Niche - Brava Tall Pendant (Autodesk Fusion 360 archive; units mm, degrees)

design "Brava Tall" references "PCB Single Pendant Canopy"
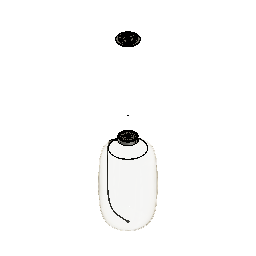
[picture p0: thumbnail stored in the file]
base_feature "Base Feature"
external_derived "ExternalDerived1" bodies "Set Screw", "Strain Relief", "Lead-1", "Lead-2", "Lead-2.1", "Lead-1.1", "Coax", "Stem"
move "Move1"
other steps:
derived_base_feature "Derived Base Feature" bodies "Set Screw", "Strain Relief", "Lead-1", "Lead-2", "Lead-2.1", "Lead-1.1", "Coax", "Stem"
create_component "CreateComponent1"
named bodies: "Set Screw", "Strain Relief", "Lead-1", "Lead-2", "Lead-2.1", "Lead-1.1", "Coax", "Stem", "Strain Relief Cap", "Nylon Gripper (2)", "Cap", "Thumbscrew (1)", "Thumbscrew (2)", "Thumbscrew (3)", "Niche-PCB", "FJ-Plug Cover", "FJ-Plug", "FJ-Plug1.1", "FJ-Plug1.2", "FJ-Plug1.3", "Fj-Plug1.4", "Canopy", "FJ-Port", "FJ-Port1.1", "Spacer", "Universal Mount", "FJ-Port Cover", "Diffuser"

design "FJ Plug - PCB-Hardware"
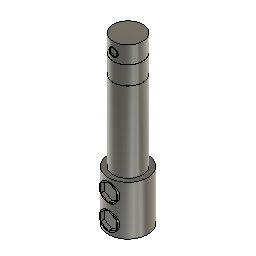
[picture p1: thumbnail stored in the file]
sketch "Sketch1" plane through (0, 0, 0) normal (0, 0, 1) x axis (1, 0, 0)
  circle C1 centre (0, 0) radius 3.048
  point P1 (0, 0)
  point P2 (0, 0)
  coincident P1 P2
  dimension "d1" diameter C1 = 6.096
extrude "Extrude1" new body sketch "Sketch1" along normal blind 34.036
sketch "Sketch2" plane through (0, 0, 0) normal (0, 0, 1) x axis (1, 0, 0)
  circle C1 centre (0, 0) radius 4.064
  point P1 (0, 0)
  point P2 (0, 0)
  coincident P1 P2
  dimension "d4" diameter C1 = 8.128
extrude "Extrude2" add sketch "Sketch2" along normal blind 10.16
sketch "Sketch3" plane through (0, 0, 0) normal (0, 1, 0) x axis (1, 0, 0)
  line L1 (6.35, 0) -> (-6.35, 0)
  line L2 (6.35, -30.48) -> (-6.35, -30.48)
  line L3 (2.54, -30.48) -> (6.35, -30.48)
  line L4 (2.54, -26.67) -> (2.54, -30.48)
  line L5 (6.35, -26.67) -> (2.54, -26.67)
  line L6 (6.35, -30.48) -> (6.35, -26.67)
  horizontal L1
  horizontal L3
  vertical L4
  horizontal L5
  vertical L6
  dimension "d7" = 30.48
revolve "Revolve1" sketch "Sketch3" AlongAngle 360
sketch "Sketch4" plane through (0, 0, 0) normal (0, 1, 0) x axis (1, 0, 0)
  line L1 (2.54, -30.48) -> (3.048, -30.48)
  line L2 (2.54, -26.67) -> (2.54, -30.48)
  line L3 (3.048, -26.67) -> (2.54, -26.67)
  line L4 (3.048, -30.48) -> (3.048, -26.67)
  horizontal L1
  vertical L2
  horizontal L3
  vertical L4
revolve "Revolve2" sketch "Sketch4" AlongAngle 360
chamfer "Chamfer1" distance 0.0254
chamfer "Chamfer2" distance 0.0254
hole "Hole1" HoleDepth 33.401 HoleDiameter 4.826 TipAngle 180
hole "Hole2" HoleDepth 3.81 HoleDiameter 1.778 TipAngle 180
hole "Hole3" HoleDepth 3.81 HoleDiameter 3.81 TipAngle 180
hole "Hole4" HoleDepth 3.81 HoleDiameter 3.81 TipAngle 180
sketch "Sketch5" plane through (0, 0, 0) normal (0, 1, 0) x axis (1, 0, 0)
  circle C1 centre (0, -32.0802) radius 0.889
  dimension "d24" diameter C1 = 1.778
extrude "Extrude3" new body sketch "Sketch5" along normal blind 1.778
move "Move1"
sketch "Sketch6" plane through (0, -3.048, 0) normal (0, -1, 0) x axis (1, 0, 0)
  line L1 (0.7259, 31.6611) -> (0, 31.242)
  line L2 (0.7259, 32.4993) -> (0.7259, 31.6611)
  line L3 (0, 32.9184) -> (0.7259, 32.4993)
  line L4 (-0.7259, 32.4993) -> (0, 32.9184)
  line L5 (-0.7259, 31.6611) -> (-0.7259, 32.4993)
  line L6 (0, 31.242) -> (-0.7259, 31.6611)
  circle C1 centre (0, 32.0802) radius 0.889
  point P2 (0, 32.0802)
  point P9 (0, 32.0802)
  coincident P2 P9
extrude "Extrude4" cut sketch "Sketch6" profile of L1 L2 L3 L4 L5 L6 against normal blind 0.254
sketch "Sketch7" plane through (0, 0, 0) normal (0, 1, 0) x axis (1, 0, 0)
  circle C1 centre (0, -2.4384) radius 1.905
  circle C2 centre (0, -7.5565) radius 1.905
  dimension "d29" diameter C1 = 3.81
  dimension "d30" diameter C2 = 3.81
extrude "Extrude5" new body sketch "Sketch7" profile of C2 along normal blind 3.81
move "Move2"
sketch "Sketch8" plane through (0, -4.064, 0) normal (0, -1, 0) x axis (1, 0, 0)
  line L1 (1.5948, 6.6357) -> (0, 5.715)
  line L2 (1.5948, 8.4772) -> (1.5948, 6.6357)
  line L3 (0, 9.398) -> (1.5948, 8.4772)
  line L4 (-1.5948, 8.4772) -> (0, 9.398)
  line L5 (-1.5948, 6.6357) -> (-1.5948, 8.4772)
  line L6 (0, 5.715) -> (-1.5948, 6.6357)
  circle C1 centre (0, 7.5565) radius 1.905
  point P2 (0, 7.5565)
  point P9 (0, 7.5565)
  coincident P2 P9
extrude "Extrude6" cut sketch "Sketch8" profile of L1 L2 L3 L4 L5 L6 against normal blind 0.762
copy_paste_bodies "CopyPasteBodies2"
move "Move4"
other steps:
base_feature "Base Feature"

design "Flask Petite"
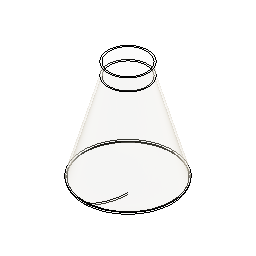
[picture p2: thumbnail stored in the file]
sketch "Sketch1" plane through (0, 0, 0) normal (1, 0, 0) x axis (0, 1, 0)
canvas "Canvas1"
sketch "Sketch2" plane through (0, 0, 0) normal (1, 0, 0) x axis (0, 1, 0)
  line L1 (-5.314, 187.093) -> (-57.384, 187.093)
  line L2 (-57.384, 155.343) -> (-57.384, 187.093)
  line L3 (-121.92, -71.12) -> (-57.384, 155.343)
  line L4 (-5.314, -112.5919) -> (-5.314, 187.093)
  curve K1 (-5.314, -112.5919) -> (-121.92, -74.8854)
  arc A1 centre (-115.3135, -73.0027) radius 6.8695 clockwise from (-121.92, -74.8854) to (-121.92, -71.12)
  point P2 (-57.384, 187.093)
  point P3 (-5.314, 187.093)
  point P4 (-57.384, 155.343)
  horizontal L1
  perpendicular L1 L2
  tangent L3 A1
  perpendicular L1 L4
  dimension "d1" distance P2 P3 = 52.07
  dimension "d2" distance P2 P4 = 31.75
revolve "Revolve1" sketch "Sketch2" AlongAngle 360
fillet "Fillet1" radius 5.08
shell "Shell1" innerThickness 4

design "PCB Single Pendant Canopy" references "PCB Cap", "Diffuser", "FJ Plug - PCB-Hardware", "Flask Petite", "PCB Canopy", "FJ Cover - PCB-Hardware"
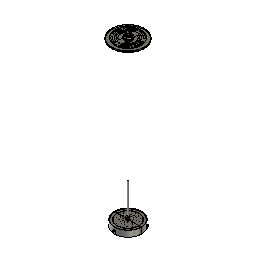
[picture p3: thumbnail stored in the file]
external_derived "ExternalDerived1" bodies "Nylon Gripper", "Set Screw", "Strain Relief", "Lead-1", "Lead-2", "Lead-2.1", "Lead-1.1", "Coax"
external_derived "ExternalDerived2" bodies "FJ-Plug Cover"
move "Move1"
move "Move2" TranslateX 3.175 TranslateY 0.254 TranslateZ 0
move "Move3" TranslateX 0 TranslateY 0 TranslateZ 1092.2
external_derived "ExternalDerived3" bodies "FJ-Plug", "FJ-Plug1.2", "FJ-Plug1.1", "FJ-Plug1.3", "Fj-Plug1.4"
move "Move4" TranslateX 0 TranslateY 0 TranslateZ 1117.6
external_derived "ExternalDerived4" bodies "Nylon Gripper", "Spacer", "Canopy", "FJ-Port", "FJ-Port1.1", "Universal Mount", "FJ-Port Cover", "Lead-1.1"
move "Move5"
move "Move6"
external_derived "ExternalDerived5" bodies "Diffuser"
move "Move7"
external_derived "ExternalDerived6" bodies "Thumbscrew (1)"
align "Align1"
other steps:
derived_base_feature "Derived Base Feature1"
derived_base_feature "Derived Base Feature2" bodies "FJ-Plug Cover"
derived_base_feature "Derived Base Feature3" bodies "FJ-Plug", "FJ-Plug1.1", "FJ-Plug1.2"
derived_base_feature "Derived Base Feature4" bodies "Body1 (1)", "Body1 (1) (1)", "Body2 (1)", "Body1 (2)", "Body1 (3)", "Body1 (4)", "Canopy", "FJ-Port"
derived_base_feature "Derived Base Feature5" bodies "Diffuser"
derived_base_feature "Derived Base Feature6" bodies "Body1", "Thumbscrew (1)"
named bodies: "Nylon Gripper", "Set Screw", "Strain Relief", "Lead-1", "Lead-2", "Lead-2.1", "Lead-1.1", "Coax", "Stem", "stem (2)", "Strain Relief Cap", "Nylon Gripper (2)", "Cap", "Thumbscrew (1)", "Thumbscrew (2)", "Thumbscrew (3)", "Niche-PCB", "FJ-Plug Cover", "FJ-Plug", "FJ-Plug1.1", "FJ-Plug1.2", "FJ-Plug1.3", "Fj-Plug1.4", "Body1 (1)", "Body1 (1) (1)", "Body2 (1)", "Body1 (2)", "Body1 (3)", "Body1 (4)", "Canopy", "FJ-Port", "FJ-Port1.1", "Spacer", "Universal Mount", "FJ-Port Cover", "Diffuser", "Body1"

design "FJ Female"
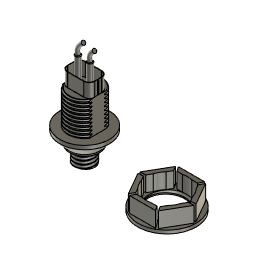
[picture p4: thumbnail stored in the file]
sketch "Sketch1" plane through (0, 0, 0) normal (0, 0, 1) x axis (1, 0, 0)
  circle C1 centre (0, 0) radius 4.445
  point P1 (0, 0)
  point P2 (0, 0)
  coincident P1 P2
  dimension "d1" diameter C1 = 8.89
extrude "Extrude1" new body sketch "Sketch1" along normal blind 6.858
sketch "Sketch2" plane through (0, 0, 6.858) normal (0, 0, 1) x axis (-1, 0, 0)
  circle C1 centre (0, 0) radius 4.445
  circle C2 centre (0, 0) radius 6.985
  point P1 (0, 0)
  point P3 (0, 0)
  coincident P1 P3
  dimension "d4" diameter C2 = 13.97
extrude "Extrude2" add sketch "Sketch2" along normal blind 1.27
work_plane "WorkPlane1" AlongDistance 5.08
sketch "Sketch3" plane through (0, 0, 13.208) normal (0, 0, 1) x axis (1, 0, 0)
  circle C1 centre (0, 0) radius 11.43
  point P1 (0, 0)
  point P2 (0, 0)
  coincident P1 P2
  dimension "d8" diameter C1 = 22.86
loft "Loft1" sketch "Sketch3"
extrude "Extrude3" add of existing geometry blind 1.778
sketch "Sketch4" plane through (0, 0, 14.986) normal (0, 0, 1) x axis (-1, 0, 0)
  circle C1 centre (0, 0) radius 11.43
  circle C2 centre (0, 0) radius 7.62
  point P1 (0, 0)
  point P3 (0, 0)
  coincident P1 P3
  dimension "d11" diameter C2 = 15.24
extrude "Extrude4" add sketch "Sketch4" profile of C2 along normal blind 15.24
sketch "Sketch5" plane through (0, 0, 30.226) normal (0, 0, 1) x axis (-1, 0, 0)
  line L1 (6.35, 0) -> (0, 0)
  line L2 (-6.35, 0) -> (0, 0)
  line L3 (6.35, -4.2121) -> (6.35, 0)
  line L4 (6.35, 4.2121) -> (6.35, 0)
  line L5 (-6.35, -4.2121) -> (-6.35, 0)
  line L6 (-6.35, 4.2121) -> (-6.35, 0)
  circle C1 centre (0, 0) radius 7.62
  point P2 (0, 0)
  point P3 (0, 0)
  point P5 (0, 0)
  point P7 (6.35, -4.2121)
  point P8 (6.35, 4.2121)
  point P9 (-6.35, -4.2121)
  point P10 (-6.35, 0)
  point P11 (-6.35, 4.2121)
  point P4 (6.35, 0)
  point P6 (-6.35, 0)
  coincident P2 P3
  horizontal L1
  coincident P2 P5
  parallel L1 L2
  coincident C1 P7
  perpendicular L1 L3
  coincident C1 P8
  perpendicular L1 L4
  coincident C1 P9
  perpendicular L2 L5
  coincident L2 P10
  perpendicular L2 L6
  coincident C1 P11
  dimension "d14" distance P3 P4 = 6.35
  dimension "d15" distance P5 P6 = 6.35
extrude "Extrude5" cut sketch "Sketch5" profile of C1 L3 L4 L5 L6 against normal blind 15.24
sketch "Sketch6" plane through (0, 0, 30.226) normal (0, 0, 1) x axis (-1, 0, 0)
  line L1 (-6.35, -4.2121) -> (-6.35, 4.2121)
  line L2 (6.35, 4.2121) -> (6.35, -4.2121)
  line L3 (-6.35, -4.2121) -> (6.35, -4.2121)
  line L4 (6.35, 4.2121) -> (-6.35, 4.2121)
  line L5 (6.35, -4.2121) -> (6.35, 4.2121)
  line L6 (-6.35, 4.2121) -> (-6.35, -4.2121)
  line L7 (-6.223, 4.064) -> (6.223, 4.064)
  line L8 (-6.223, -4.064) -> (-6.223, 4.064)
  line L9 (6.223, -4.064) -> (-6.223, -4.064)
  line L10 (6.223, 4.064) -> (6.223, -4.064)
  line L11 (-6.223, -4.064) -> (6.223, 4.064)
  line L12 (6.223, -4.064) -> (-6.223, 4.064)
  arc A1 centre (0, 0) radius 7.62 clockwise from (6.35, -4.2121) to (-6.35, -4.2121)
  arc A2 centre (0, 0) radius 7.62 clockwise from (-6.35, 4.2121) to (6.35, 4.2121)
  point P4 (6.35, -4.2121)
  point P7 (6.35, -4.2121)
  point P3 (-6.35, -4.2121)
  point P8 (-6.35, -4.2121)
  point P2 (-6.35, 4.2121)
  point P9 (-6.35, 4.2121)
  point P6 (6.35, 4.2121)
  point P10 (6.35, 4.2121)
  point P15 (0, 0)
  point P5 (0, 0)
  point P13 (-6.223, -4.064)
  point P14 (6.223, -4.064)
  point P12 (-6.223, 4.064)
  coincident P4 P7
  coincident P3 P8
  coincident P2 P9
  coincident P6 P10
  perpendicular L7 L8
  parallel L7 L9
  parallel L8 L10
  horizontal L7
  coincident L11 P15
  coincident L12 P15
  coincident P5 P15
  dimension "d18" distance P13 P14 = 12.446
  dimension "d19" distance P12 P13 = 8.128
extrude "Extrude6" add sketch "Sketch6" profile of L1 L2 L3 L4 L5 L6 L7 L8 L9 L10 along normal blind 6.35
fillet "Fillet1" radius 2.54
sketch "Sketch7" plane through (6.35, 0, 0) normal (1, 0, 0) x axis (0, 1, 0)
  line L1 (1.6721, 36.576) -> (1.6721, 30.226)
  line L2 (-1.6721, 36.576) -> (1.6721, 36.576)
  line L3 (-1.6721, 30.226) -> (-1.6721, 36.576)
  line L4 (-4.2121, 30.226) -> (-1.6721, 30.226)
  line L5 (-4.2121, 14.986) -> (-4.2121, 30.226)
  line L6 (4.2121, 14.986) -> (-4.2121, 14.986)
  line L7 (4.2121, 30.226) -> (4.2121, 14.986)
  line L8 (1.6721, 30.226) -> (4.2121, 30.226)
  line L9 (0.254, 36.576) -> (-0.2492, 36.576)
  line L10 (0.254, 30.226) -> (0.254, 36.576)
  line L11 (-0.2492, 30.226) -> (0.254, 30.226)
  line L12 (-0.2492, 36.576) -> (-0.2492, 30.226)
  point P10 (-0.2492, 36.576)
  horizontal L9
  vertical L10
  horizontal L11
  vertical L12
  coincident L2 P10
extrude "Extrude7" cut sketch "Sketch7" profile of L2 L9 L10 L11 L12 against normal blind 0.508
thread "Thread1"
fillet "Fillet2" radius 0.635
thread "Thread2"
sketch "Sketch8" plane through (0, 0, 30.226) normal (0, 0, 1) x axis (-1, 0, 0)
  line L1 (-6.223, -1.524) -> (-6.223, -0.254)
  line L2 (3.683, -4.064) -> (-3.683, -4.064)
  line L3 (6.223, 1.524) -> (6.223, -1.524)
  line L4 (-3.683, 4.064) -> (3.683, 4.064)
  line L5 (-6.223, 0.2492) -> (-6.223, 1.524)
  line L6 (-6.35, 0.2492) -> (-6.223, 0.2492)
  line L7 (-6.35, -0.254) -> (-6.35, 0.2492)
  line L8 (-6.223, -0.254) -> (-6.35, -0.254)
  arc A1 centre (-3.683, -1.524) radius 2.54 clockwise from (-3.683, -4.064) to (-6.223, -1.524)
  arc A2 centre (3.683, -1.524) radius 2.54 clockwise from (6.223, -1.524) to (3.683, -4.064)
  arc A3 centre (3.683, 1.524) radius 2.54 clockwise from (3.683, 4.064) to (6.223, 1.524)
  arc A4 centre (-3.683, 1.524) radius 2.54 clockwise from (-6.223, 1.524) to (-3.683, 4.064)
  circle C1 centre (3.048, 0) radius 1.27
  circle C2 centre (-2.54, 0) radius 1.27
  dimension "d26" diameter C1 = 2.54
  dimension "d27" diameter C2 = 2.54
extrude "Extrude8" add sketch "Sketch8" profile of C1 C2 along normal blind 11.43
sketch "Sketch9" plane through (0, 0, 0) normal (0, 1, 0) x axis (1, 0, 0)
  curve K1 (4.572, -46.99) -> (2.54, -41.656)
  curve K2 (-0.508, -47.752) -> (-3.048, -41.656)
pipe "Pipe1" SectionSize 1.778 SectionThickness 0.0762
pipe "Pipe2" SectionSize 1.778 SectionThickness 0.0762
sketch "Sketch10" plane through (0, 0, 0) normal (0, 0, 1) x axis (1, 0, 0)
  circle C1 centre (38.1, 0) radius 13.462
  dimension "d38" diameter C1 = 26.924
extrude "Extrude9" new body sketch "Sketch10" along normal blind 1.524
sketch "Sketch11" plane through (0, 0, 1.524) normal (0, 0, 1) x axis (-1, 0, 0)
  circle C1 centre (-38.1, 0) radius 13.462
  circle C2 centre (-38.1, 0) radius 9.271
  concentric C1 C2
  dimension "d41" diameter C2 = 18.542
extrude "Extrude10" cut sketch "Sketch11" profile of C2 against normal blind 7.62
sketch "Sketch12" plane through (0, 0, 1.524) normal (0, 0, 1) x axis (-1, 0, 0)
  line L1 (-24.9018, 0) -> (-31.5009, -11.43)
  line L2 (-31.5009, 11.43) -> (-24.9018, 0)
  line L3 (-44.6991, 11.43) -> (-31.5009, 11.43)
  line L4 (-51.2982, 0) -> (-44.6991, 11.43)
  line L5 (-44.6991, -11.43) -> (-51.2982, 0)
  line L6 (-31.5009, -11.43) -> (-44.6991, -11.43)
  line L7 (-27.3948, 0) -> (-32.7474, -9.271)
  line L8 (-32.7474, 9.271) -> (-27.3948, 0)
  line L9 (-43.4526, 9.271) -> (-32.7474, 9.271)
  line L10 (-48.8052, 0) -> (-43.4526, 9.271)
  line L11 (-43.4526, -9.271) -> (-48.8052, 0)
  line L12 (-32.7474, -9.271) -> (-43.4526, -9.271)
  circle C1 centre (-38.1, 0) radius 9.271
  circle C2 centre (-38.1, 0) radius 13.462
  point P2 (-38.1, 0)
  point P9 (-38.1, 0)
  point P16 (-38.1, 0)
  coincident P2 P9
  coincident P9 P16
extrude "Extrude11" add sketch "Sketch12" profile of L1 L2 L3 L4 L5 L6 L7 L8 L9 L10 L11 L12 along normal blind 7.112
thread "Thread3"
sketch "Sketch13" plane through (0, 0, 8.636) normal (0, 0, 1) x axis (-1, 0, 0)
  line L1 (-43.4526, -9.271) -> (-32.7474, -9.271)
  line L2 (-48.8052, 0) -> (-43.4526, -9.271)
  line L3 (-43.4526, 9.271) -> (-48.8052, 0)
  line L4 (-32.7474, 9.271) -> (-43.4526, 9.271)
  line L5 (-27.3948, 0) -> (-32.7474, 9.271)
  line L6 (-32.7474, -9.271) -> (-27.3948, 0)
  line L7 (-31.5009, -11.43) -> (-44.6991, -11.43)
  line L8 (-24.9018, 0) -> (-31.5009, -11.43)
  line L9 (-31.5009, 11.43) -> (-24.9018, 0)
  line L10 (-44.6991, 11.43) -> (-31.5009, 11.43)
  line L11 (-51.2982, 0) -> (-44.6991, 11.43)
  line L12 (-44.6991, -11.43) -> (-51.2982, 0)
sketch "Sketch14" plane through (0, 0, 8.636) normal (0, 0, 1) x axis (-1, 0, 0)
  circle C1 centre (-38.1, 0) radius 9.525
  dimension "d46" diameter C1 = 19.05
extrude "Extrude12" cut sketch "Sketch14" against normal blind 7.112
sketch "Sketch15" plane through (0, 0, 8.636) normal (0, 0, 1) x axis (-1, 0, 0)
  line L1 (-51.2982, 0) -> (-44.6991, 11.43)
  line L2 (-43.4526, 9.271) -> (-48.8052, 0)
  line L3 (-32.7474, 9.271) -> (-43.4526, 9.271)
  line L4 (-44.6991, 11.43) -> (-31.5009, 11.43)
  line L5 (-44.1911, 11.43) -> (-42.7995, 9.271)
  line L6 (-40.2139, 9.271) -> (-42.7995, 9.271)
  line L7 (-43.7181, 8.8112) -> (-45.0232, 10.8687)
  line L8 (-43.4526, 9.271) -> (-42.7995, 9.271)
  line L9 (-43.7181, 8.8112) -> (-43.4526, 9.271)
  line L10 (-45.0232, 10.8687) -> (-44.6991, 11.43)
  line L11 (-44.1911, 11.43) -> (-44.6991, 11.43)
  line L12 (-48.5398, -0.4598) -> (-50.9742, -0.5613)
  line L13 (-48.5398, -0.4598) -> (-48.8052, 0)
  line L14 (-48.8052, 0) -> (-48.4787, 0.5657)
  line L15 (-51.0442, 0.4399) -> (-48.4787, 0.5657)
  line L16 (-51.0442, 0.4399) -> (-51.2982, 0)
  line L17 (-50.9742, -0.5613) -> (-51.2982, 0)
  line L18 (-42.9217, -9.271) -> (-44.051, -11.43)
  line L19 (-42.9217, -9.271) -> (-43.4526, -9.271)
  line L20 (-43.4526, -9.271) -> (-43.7792, -8.7053)
  line L21 (-44.9531, -10.9901) -> (-43.7792, -8.7053)
  line L22 (-44.9531, -10.9901) -> (-44.6991, -11.43)
  line L23 (-44.051, -11.43) -> (-44.6991, -11.43)
  line L24 (-32.4819, -8.8112) -> (-31.1768, -10.8687)
  line L25 (-32.4819, -8.8112) -> (-32.7474, -9.271)
  line L26 (-32.7474, -9.271) -> (-33.4005, -9.271)
  line L27 (-32.0089, -11.43) -> (-33.4005, -9.271)
  line L28 (-32.0089, -11.43) -> (-31.5009, -11.43)
  line L29 (-31.1768, -10.8687) -> (-31.5009, -11.43)
  line L30 (-27.6603, 0.4598) -> (-25.2258, 0.5613)
  line L31 (-27.6603, 0.4598) -> (-27.3948, 0)
  line L32 (-27.3948, 0) -> (-27.7214, -0.5657)
  line L33 (-25.1558, -0.4399) -> (-27.7214, -0.5657)
  line L34 (-25.1558, -0.4399) -> (-24.9018, 0)
  line L35 (-25.2258, 0.5613) -> (-24.9018, 0)
  line L36 (-33.2783, 9.271) -> (-32.149, 11.43)
  line L37 (-33.2783, 9.271) -> (-32.7474, 9.271)
  line L38 (-32.7474, 9.271) -> (-32.4208, 8.7053)
  line L39 (-31.2469, 10.9901) -> (-32.4208, 8.7053)
  line L40 (-31.2469, 10.9901) -> (-31.5009, 11.43)
  line L41 (-32.149, 11.43) -> (-31.5009, 11.43)
  point P10 (-42.7995, 9.271)
  point P12 (-45.0232, 10.8687)
  point P13 (-43.7181, 8.8112)
  point P5 (-43.4526, 9.271)
  point P14 (-43.4526, 9.271)
  point P16 (-44.1911, 11.43)
  point P9 (-44.6991, 11.43)
  point P15 (-44.6991, 11.43)
  horizontal L6
  coincident L3 P10
  coincident L1 P12
  coincident L2 P13
  coincident P5 P14
  coincident L4 P16
  coincident P9 P15
  coincident L4 P16
  dimension "d50" distance P15 P16 = 0.508
  dimension "d54" C-Pattern1-Angle = 360
extrude "Extrude13" cut sketch "Sketch15" profile of L1 L2 L3 L4 L5 L7 L8 L9 L10 L11 L12 L13 L14 L15 L16 L17 L18 L19 L20 L21 L22 L23 L24 L25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 against normal blind 7.112

design "FJ Cover - PCB-Hardware"
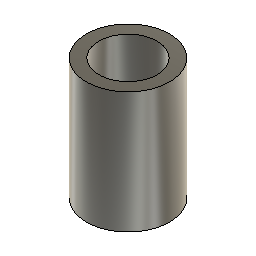
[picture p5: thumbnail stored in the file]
sketch "Sketch1" plane through (0, 0, 0) normal (0, 0, 1) x axis (1, 0, 0)
  circle C1 centre (0, 0) radius 6.35
  point P1 (0, 0)
  point P2 (0, 0)
  coincident P1 P2
  dimension "d1" diameter C1 = 12.7
extrude "Extrude1" new body sketch "Sketch1" along normal blind 18.542
hole "Hole1" HoleDepth 13.97 HoleDiameter 8.89 TipAngle 180
hole "Hole2" HoleDepth 13.97 HoleDiameter 3.556 TipAngle 180

design "PCB Canopy" references "Port Cover - PCB-Hardware", "Spacer - PCB-Hardware", "FJ Female", "FJ Cover - PCB-Hardware", "Canopy - PCB-Hardware", "Universal Mounting Bracket - PCB-Hardware"
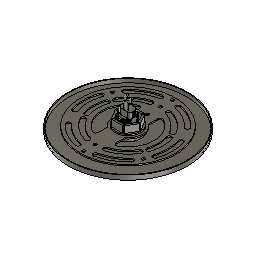
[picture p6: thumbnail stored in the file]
external_derived "ExternalDerived"
external_derived "ExternalDerived"
external_derived "ExternalDerived3" bodies "Body1 (1)"
external_derived "ExternalDerived4"
external_derived "ExternalDerived5"
move "Move1"
move "Move2"
move "Move3"
move "Move4"
move "Move5"
move "Move6"
move "Move7"
move "Move8"
external_derived "ExternalDerived6"
align "Align1"
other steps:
derived_base_feature "Derived Base Feature" bodies "Body1"
derived_base_feature "Derived Base Feature" bodies "Body1 (1)", "Body2"
derived_base_feature "Derived Base Feature3" bodies "Body1 (2)", "Body1 (1)"
derived_base_feature "Derived Base Feature4" bodies "Body1 (3)"
derived_base_feature "Derived Base Feature5" bodies "Body1 (4)"
derived_base_feature "Derived Base Feature6" bodies "Body1 (5)"
named bodies: "Body1", "Body1 (1)", "Body2", "Body1 (2)", "Body1 (3)", "Body1 (4)", "Body1 (5)"

design "Spacer - PCB-Hardware"
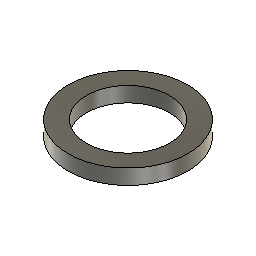
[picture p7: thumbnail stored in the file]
sketch "Sketch1" plane through (0, 0, 0) normal (0, 0, 1) x axis (1, 0, 0)
  circle C1 centre (0, 0) radius 14.097
  circle C2 centre (0, 0) radius 9.779
  point P1 (0, 0)
  point P2 (0, 0)
  point P3 (0, 0)
  coincident P1 P2
  coincident P1 P3
  dimension "d1" diameter C1 = 28.194
  dimension "d2" diameter C2 = 19.558
extrude "Extrude1" new body sketch "Sketch1" along normal blind 3.556

design "Universal Mounting Bracket - PCB-Hardware"
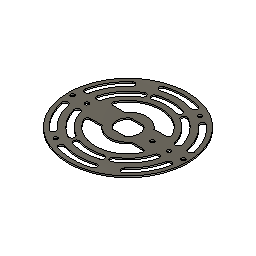
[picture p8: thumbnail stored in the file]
sketch "Sketch1" plane through (0, 0, 0) normal (0, 0, 1) x axis (1, 0, 0)
  circle C1 centre (0, 0) radius 50.8
  arc A1 centre (0, 0) radius 42.545 clockwise from (-13.1471, 40.4627) to (13.1471, 40.4627)
  arc A2 centre (0, 0) radius 47.371 clockwise from (-14.6384, 45.0525) to (14.6384, 45.0525)
  arc A3 centre (-13.8928, 42.7576) radius 2.413 clockwise from (-13.1471, 40.4627) to (-14.6384, 45.0525)
  arc A4 centre (13.8928, 42.7576) radius 2.413 clockwise from (14.6384, 45.0525) to (13.1471, 40.4627)
  arc A5 centre (0, 0) radius 47.371 clockwise from (-46.3358, 9.849) to (-31.6974, 35.2035)
  arc A6 centre (0, 0) radius 42.545 clockwise from (-41.6153, 8.8456) to (-28.4682, 31.6171)
  arc A7 centre (-43.9756, 9.3473) radius 2.413 clockwise from (-41.6153, 8.8456) to (-46.3358, 9.849)
  arc A8 centre (-30.0828, 33.4103) radius 2.413 clockwise from (-31.6974, 35.2035) to (-28.4682, 31.6171)
  arc A9 centre (0, 0) radius 47.371 clockwise from (-31.6974, -35.2035) to (-46.3358, -9.849)
  arc A10 centre (0, 0) radius 42.545 clockwise from (-28.4682, -31.6171) to (-41.6153, -8.8456)
  arc A11 centre (-30.0828, -33.4103) radius 2.413 clockwise from (-28.4682, -31.6171) to (-31.6974, -35.2035)
  arc A12 centre (-43.9756, -9.3473) radius 2.413 clockwise from (-46.3358, -9.849) to (-41.6153, -8.8456)
  arc A13 centre (0, 0) radius 47.371 clockwise from (14.6384, -45.0525) to (-14.6384, -45.0525)
  arc A14 centre (0, 0) radius 42.545 clockwise from (13.1471, -40.4627) to (-13.1471, -40.4627)
  arc A15 centre (13.8928, -42.7576) radius 2.413 clockwise from (13.1471, -40.4627) to (14.6384, -45.0525)
  arc A16 centre (-13.8928, -42.7576) radius 2.413 clockwise from (-14.6384, -45.0525) to (-13.1471, -40.4627)
  arc A17 centre (0, 0) radius 47.371 clockwise from (46.3358, -9.849) to (31.6974, -35.2035)
  arc A18 centre (0, 0) radius 42.545 clockwise from (41.6153, -8.8456) to (28.4682, -31.6171)
  arc A19 centre (43.9756, -9.3473) radius 2.413 clockwise from (41.6153, -8.8456) to (46.3358, -9.849)
  arc A20 centre (30.0828, -33.4103) radius 2.413 clockwise from (31.6974, -35.2035) to (28.4682, -31.6171)
  arc A21 centre (0, 0) radius 47.371 clockwise from (31.6974, 35.2035) to (46.3358, 9.849)
  arc A22 centre (0, 0) radius 42.545 clockwise from (28.4682, 31.6171) to (41.6153, 8.8456)
  arc A23 centre (30.0828, 33.4103) radius 2.413 clockwise from (28.4682, 31.6171) to (31.6974, 35.2035)
  arc A24 centre (43.9756, 9.3473) radius 2.413 clockwise from (46.3358, 9.849) to (41.6153, 8.8456)
  arc A25 centre (0, 0) radius 32.385 clockwise from (-31.2224, 8.5995) to (-16.1925, 28.0462)
  arc A26 centre (0, 0) radius 37.338 clockwise from (-35.9514, 10.0809) to (-18.669, 32.3357)
  arc A27 centre (0, 0) radius 32.385 clockwise from (16.1925, 28.0462) to (31.2224, 8.5995)
  arc A28 centre (0, 0) radius 32.385 clockwise from (-10.0075, 30.8) to (10.0075, 30.8)
  arc A29 centre (0, 0) radius 37.338 clockwise from (18.669, 32.3357) to (35.9514, 10.0809)
  arc A30 centre (0, 0) radius 37.338 clockwise from (-11.5381, 35.5105) to (11.5381, 35.5105)
  arc A31 centre (-33.5467, 9.4685) radius 2.4814 clockwise from (-31.1111, 8.9939) to (-35.9167, 10.2037)
  arc A32 centre (-17.4307, 30.1909) radius 2.4765 clockwise from (-18.669, 32.3357) to (-16.1925, 28.0462)
  arc A33 centre (-10.7728, 33.1553) radius 2.4765 clockwise from (-10.0075, 30.8) to (-11.5381, 35.5105)
  arc A34 centre (10.7728, 33.1553) radius 2.4765 clockwise from (11.5381, 35.5105) to (10.0075, 30.8)
  arc A35 centre (17.4307, 30.1909) radius 2.4765 clockwise from (16.1925, 28.0462) to (18.669, 32.3357)
  arc A36 centre (33.5467, 9.4685) radius 2.4814 clockwise from (35.9167, 10.2037) to (31.1111, 8.9939)
  arc A37 centre (-33.5467, -9.4685) radius 2.4814 clockwise from (-35.9167, -10.2037) to (-31.1111, -8.9939)
  arc A38 centre (0, 0) radius 37.338 clockwise from (-18.669, -32.3357) to (-35.9514, -10.0809)
  arc A39 centre (0, 0) radius 32.385 clockwise from (-16.1925, -28.0462) to (-31.2224, -8.5995)
  arc A40 centre (-17.4307, -30.1909) radius 2.4765 clockwise from (-16.1925, -28.0462) to (-18.669, -32.3357)
  arc A41 centre (-10.7728, -33.1553) radius 2.4765 clockwise from (-11.5381, -35.5105) to (-10.0075, -30.8)
  arc A42 centre (0, 0) radius 37.338 clockwise from (11.5381, -35.5105) to (-11.5381, -35.5105)
  arc A43 centre (0, 0) radius 32.385 clockwise from (10.0075, -30.8) to (-10.0075, -30.8)
  arc A44 centre (10.7728, -33.1553) radius 2.4765 clockwise from (10.0075, -30.8) to (11.5381, -35.5105)
  arc A45 centre (17.4307, -30.1909) radius 2.4765 clockwise from (18.669, -32.3357) to (16.1925, -28.0462)
  arc A46 centre (0, 0) radius 37.338 clockwise from (35.9514, -10.0809) to (18.669, -32.3357)
  arc A47 centre (0, 0) radius 32.385 clockwise from (31.2224, -8.5995) to (16.1925, -28.0462)
  arc A48 centre (33.5467, -9.4685) radius 2.4814 clockwise from (31.1111, -8.9939) to (35.9167, -10.2037)
  point P1 (0, 0)
  point P2 (0, 0)
  point P71 (-35.9514, 10.0809)
  point P72 (-31.2224, 8.5995)
  point P73 (35.9514, 10.0809)
  point P74 (31.2224, 8.5995)
  point P75 (-31.1111, 8.9939)
  point P76 (-35.9167, 10.2037)
  point P77 (35.9167, 10.2037)
  point P78 (31.1111, 8.9939)
  coincident P1 P2
  concentric C1 A2
  concentric A1 A2
  concentric A17 A26
  concentric A25 A26
  concentric A25 A27
  concentric A26 A29
  concentric A27 A28
  concentric A29 A30
  coincident P71 A31
  coincident P72 A31
  coincident P73 A36
  coincident P74 A36
  coincident A25 P75
  coincident A26 P76
  coincident A29 P77
  coincident A27 P78
  dimension "d1" diameter C1 = 101.6
  dimension "d2" diameter A2 = 94.742
  dimension "d11" diameter A26 = 74.676
  dimension "d12" diameter A25 = 64.77
  dimension "d10" C-Pattern1-Angle = 360
sketch "Sketch2" plane through (0, 0, 0) normal (0, 0, 1) x axis (1, 0, 0)
  line L1 (5.3986, -8.001) -> (-5.3986, -8.001)
  line L2 (5.3986, 8.001) -> (-5.3986, 8.001)
  arc A1 centre (0, 0) radius 9.652 clockwise from (-5.3986, -8.001) to (-5.3986, 8.001)
  arc A2 centre (0, 0) radius 9.652 clockwise from (5.3986, 8.001) to (5.3986, -8.001)
  point P1 (0, 0)
  point P2 (0, 0)
  coincident P1 P2
  concentric A1 A2
  dimension "d6" diameter A1 = 19.304
sketch "Sketch3" plane through (0, 0, 0) normal (0, 0, 1) x axis (1, 0, 0)
  line L1 (-12.5409, 9.525) -> (-22.2072, 9.525)
  line L2 (22.2072, 9.525) -> (12.5409, 9.525)
  line L3 (-12.5409, -9.525) -> (-22.2072, -9.525)
  line L4 (22.2072, -9.525) -> (12.5409, -9.525)
  arc A1 centre (0, 0) radius 15.748 clockwise from (12.5409, -9.525) to (-12.5409, -9.525)
  arc A2 centre (0, 0) radius 15.748 clockwise from (-12.5409, 9.525) to (12.5409, 9.525)
  arc A3 centre (0, 0) radius 27.813 clockwise from (24.4391, -13.2776) to (-24.4391, -13.2776)
  arc A4 centre (0, 0) radius 27.813 clockwise from (-24.4391, 13.2776) to (24.4391, 13.2776)
  arc A5 centre (-22.2072, 12.065) radius 2.54 clockwise from (-22.2072, 9.525) to (-24.4391, 13.2776)
  arc A6 centre (22.2072, 12.065) radius 2.54 clockwise from (24.4391, 13.2776) to (22.2072, 9.525)
  arc A7 centre (-22.2072, -12.065) radius 2.54 clockwise from (-24.4391, -13.2776) to (-22.2072, -9.525)
  arc A8 centre (22.2072, -12.065) radius 2.54 clockwise from (22.2072, -9.525) to (24.4391, -13.2776)
  point P1 (0, 0)
  point P2 (0, 0)
  point P5 (12.5409, 9.525)
  coincident P1 P2
  concentric A1 A3
  coincident P5 A1
  collinear L1 L2
  collinear L3 L4
  concentric A1 A2
  concentric A3 A4
  tangent L1 A5
  tangent A4 A5
  tangent L2 A6
  tangent A4 A6
  equal A5 A6
  tangent L3 A7
  tangent A3 A7
  equal A5 A7
  tangent L4 A8
  tangent A3 A8
  equal A5 A8
  dimension "d17" diameter A3 = 55.626
  dimension "d18" diameter A1 = 31.496
  dimension "d37" radius A5 = 2.54
sketch "Sketch4" plane through (0, 0, 0) normal (0, 0, 1) x axis (1, 0, 0)
  circle C1 centre (22.479, 38.9348) radius 1.651
  circle C2 centre (-22.479, -38.9348) radius 1.651
  circle C3 centre (-34.8615, 0) radius 1.651
  circle C4 centre (-47.117, 0) radius 1.651
  circle C5 centre (34.8615, 0) radius 1.651
  circle C6 centre (47.117, 0) radius 1.651
  circle C7 centre (20.701, 0) radius 1.651
  dimension "d36" diameter C7 = 3.302
  dimension "d25" C-Pattern2-Angle = 180
extrude "Extrude1" new body sketch "Sketch1" profile of C1 A2 A1 A3 A4 A5 A6 A7 A8 A9 A10 A11 A12 A13 A14 A15 A16 A17 A18 A19 A20 A21 A22 A23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 along normal blind 1.27
extrude "Extrude2" cut sketch "Sketch3" + "Sketch2" profile of S2:A2 S2:L1 S2:L2 S1:A4 S1:A2 S1:L4 S1:L2 S1:A5 S1:A6 S1:A7 S1:A8 blind 1.27
extrude "Extrude3" cut sketch "Sketch4" along normal blind 1.27

design "Port Cover - PCB-Hardware"
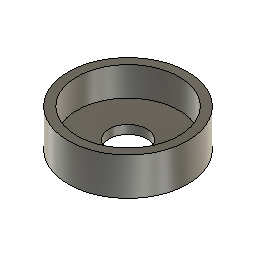
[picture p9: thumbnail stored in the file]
sketch "Sketch1" plane through (0, 0, 0) normal (0, 0, 1) x axis (1, 0, 0)
  circle C1 centre (0, 0) radius 14.097
  point P1 (0, 0)
  point P2 (0, 0)
  coincident P1 P2
  dimension "d1" diameter C1 = 28.194
extrude "Extrude1" new body sketch "Sketch1" along normal blind 8.89
shell "Shell1" innerThickness 2.032
hole "Hole1" HoleDepth 22.86 HoleDiameter 8.89 TipAngle 118

design "PCB Cap"
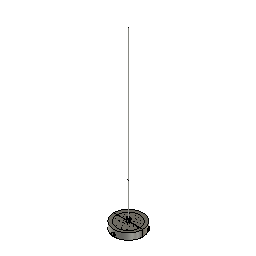
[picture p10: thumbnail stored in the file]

design "Canopy - PCB-Hardware"
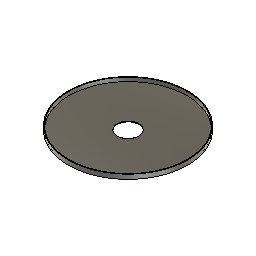
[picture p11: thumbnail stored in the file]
sketch "Sketch1" plane through (0, 0, 0) normal (0, 0, 1) x axis (1, 0, 0)
  circle C1 centre (0, 0) radius 63.5
  point P1 (0, 0)
  point P2 (0, 0)
  coincident P1 P2
extrude "Extrude1" new body sketch "Sketch1" along normal blind 4.826
shell "Shell1" innerThickness 0.762
hole "Hole1" HoleDepth 22.86 HoleDiameter 22.86 TipAngle 118

design "Diffuser"
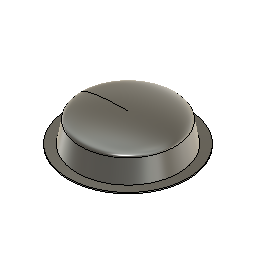
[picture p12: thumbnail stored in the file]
sketch "Sketch1" plane through (0, 0, 0) normal (0, 1, 0) x axis (1, 0, 0)
sketch "Sketch2" plane through (0, 0, 0) normal (0, 0, 1) x axis (1, 0, 0)
  circle C1 centre (0, 0) radius 43.18
  point P1 (0, 0)
  point P2 (0, 0)
  coincident P1 P2
  dimension "d1" diameter C1 = 86.36
sketch "Sketch4" plane through (0, 0, 0) normal (0, 0, 1) x axis (1, 0, 0)
  circle C1 centre (0, 0) radius 50.8
  point P1 (0, 0)
  point P2 (0, 0)
  coincident P1 P2
  dimension "d2" diameter C1 = 101.6
extrude "Extrude1" new body sketch "Sketch4" along normal blind 1.016
sketch "Sketch5" plane through (0, 0, 1.016) normal (0, 0, 1) x axis (-1, 0, 0)
  circle C1 centre (0, 0) radius 50.8
  circle C2 centre (0, 0) radius 42.545
  concentric C1 C2
  dimension "d5" diameter C2 = 85.09
sketch "Sketch8" plane through (0, 0, 1.016) normal (0, 0, 1) x axis (-1, 0, 0)
  circle C1 centre (0, 0) radius 42.545
sketch "Sketch11" plane through (0, 0, 0) normal (0, 1, 0) x axis (1, 0, 0)
sketch "Sketch14" plane through (0, 0, 0) normal (0, 1, 0) x axis (1, 0, 0)
sketch "Sketch15" plane through (0, 0, 1.016) normal (0, 0, 1) x axis (-1, 0, 0)
  line L1 (-42.545, 0) -> (0, 0)
  circle C1 centre (0, 0) radius 42.545
  point P1 (0, 0)
  point P3 (0, 0)
  point P4 (-42.545, 0)
  coincident P1 P3
  coincident C1 P4
  horizontal L1
sketch "Sketch16" plane through (0, 0, 0) normal (0, 0, -1) x axis (1, 0, 0)
  circle C1 centre (0, 0) radius 50.8
sketch "Sketch17" plane through (0, 0, 0) normal (0, 1, 0) x axis (1, 0, 0)
  line L1 (0, -18.8361) -> (40.0012, -18.8361)
  line L2 (0, -1.016) -> (43.18, -1.016)
  line L3 (40.0012, -18.8361) -> (43.18, -1.016)
  line L4 (0, -1.016) -> (0, -25.146)
  line L5 (0, -1.016) -> (43.18, -1.016)
  line L6 (0, -25.1861) -> (0, -1.016)
  curve K1 (0, -25.1861) -> (0, -12.4861)
  curve K2 (40.0012, -18.8361) -> (-40.0012, -18.8361)
  line L7 (0, -12.4861) -> (0, -25.146)
  closed curve K3 centre (0, -18.8361)
  point P3 (0, -1.016)
  point P6 (0, -1.016)
  point P9 (0, -1.016)
  point P10 (0, -1.016)
  point P8 (0, -12.4861)
  point P7 (0, -25.1861)
  point P14 (-40.0012, -18.8361)
  point P11 (40.0012, -18.8361)
  point P4 (43.18, -1.016)
  coincident P3 P6
  coincident P3 P9
  perpendicular L2 L4
  coincident P3 P10
  perpendicular L5 L6
  horizontal L1
  perpendicular L1 K1
  coincident P8 K3
  coincident P7 K3
  coincident K3 P14
  coincident P11 K3
  parallel K1 L7
  dimension "d17" distance P3 P4 = 43.18
revolve "Revolve4" sketch "Sketch17" AlongAngle 360
shell "Shell5" innerThickness 1.016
